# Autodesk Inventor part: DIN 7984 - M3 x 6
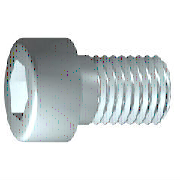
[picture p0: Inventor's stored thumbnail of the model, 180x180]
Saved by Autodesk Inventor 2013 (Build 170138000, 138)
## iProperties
IsCustomPart: 0
Created: 2012-02
Part Number: DIN 7984 - M3 x 6
Material: Steel, Mild
Description: Cylinder Head Cap Screw
Document SubType Name: Modeling
Standard: DIN 7984
Designer: rYan
Standard Revision: 1985
Standards Organization: DIN
Language: en-US
Size Designation: M3 x 6
Categories: <MemberInstance><Categories><Category DisplayName="Fasteners" InternalName="e4da775c-781d-43d5-af7c-5136215cf5a6" Mnemonic="FSTN"><Category DisplayName="Bolts"
Density: 7.86 g/cm^3
Mass: 0.653232 g
Surface Area: 1.45477 cm^2
Volume: 0.0831084 cm^3
Author: rYan
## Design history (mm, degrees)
sketch "Sketch1"
  geometry: L1 (0.167, 0)-(6, 0); L2 (6, 0)-(6, 1.5); L3 (6, 1.5)-(1.5, 1.5); L4 (1.5, 1.5)-(1.193, 1.5); L5 (1.193, 1.5)-(0, 1.5); L6 (0, 1.5)-(0, 2.75); L7 (0, 2.75)-(-2, 2.75); L8 (-2, 2.75)-(-2, 1.155); L9 (-2, 1.155)-(-0.5, 1.155); L10 (-0.5, 1.155)-(0.167, 0); L11 (-3.6, 0)-(7.6, 0) reference; L12 (0, -0.55)-(0, 3.3) reference; L13 (1.5, 1.5)-(0, 1.5)
  constraints: 22 end point, 6 parallel, 2 collinear, 2 perpendicular, 1 horizontal, 1 point on line
  dimensions: "d1" = 4.5 distance from line of L3.end L2 (= GEL); "d2" = 0.30683 distance of L4.end L3.end (computed from GAL); "d3" = 2 distance between parallel lines of L8 L6 (= KOH); "d4" = 1.5 distance of L8.end L9.end (= INTI); "d5" = 60 deg angle of L10 L1; "d6" = 3 diameter of L3 L1 (= GD); "d7" = 3 diameter of L5 L1 (= BDM); "d8" = 2.3094 diameter of L9 L1 (= 1.1547 x SW); "d9" = 5.5 diameter of L7 L1 (= KOD); "d26" = 6 distance between parallel lines of L12 L2 (= NLG)
revolve "Body" sketch "Sketch1" stored, may be unused: angle "d10" = 90 deg
sketch "Sketch2"
  geometry: L1 (0, -3.85)-(0, 3.85) reference; L2 (-3.85, 0)-(3.85, 0) reference; L3 (1.155, 0)-(0.577, -1); L4 (0.577, -1)-(-0.577, -1); L5 (-0.577, -1)-(-1.155, 0); L6 (-1.155, 0)-(-0.577, 1); L7 (-0.577, 1)-(0.577, 1); L8 (0.577, 1)-(1.155, 0); 2 further points
  constraints: 12 end point, 1 coincident, 1 horizontal alignment, 1 point on line, 12 other
extrude "Slot" join sketch "Sketch2" stored distance "d11" = 10; taper "d12" = 0 deg
workplane "Work Plane1"
fillet "Fillet2" dims "d30" = 0.1 (= R)
body "Solid1"
fillet "Fillet1" dims "d17" = 0.3 (= RR)
feature "Thread" dims "d13" = 4.5 (= GEL), "d14" = 0
chamfer "Chamfer1" distance "d15" = 0.30673 (= -0.5 x SPD + 0.5 x GD); stored, may be unused: second distance "d16" = 0.30673 (= GUL), angle "d27" = 45 deg
other parameters: "GD" = 3 (= NND) [user parameter; used in 2 equation terms], "NLG" = 6 [user parameter; used in 1 equation term], "GEL" = 4.5 [user parameter; used in 2 equation terms], "KOD" = 5.5 [user parameter; used in 1 equation term], "KOH" = 2 [user parameter; used in 1 equation term], "INTI" = 1.5 [user parameter; used in 1 equation term], "GAL" = 0.30673 (= 0.61345 x PTC) [user parameter; used in 1 equation term], "GUL" = 0.30673 (= 0.61345 x PTC) [user parameter; used in 1 equation term], "BDM" = 3 (= NND) [user parameter; used in 1 equation term], "SW" = 2 [user parameter; used in 2 equation terms], "RR" = 0.3 [user parameter; used in 1 equation term], "SPD" = 2.38655 (= NND - 1.2269 x PTC) [user parameter; used in 1 equation term], "d19" = 0, "d28" = 0, "d29" = 0, "R" = 0.1 [user parameter; used in 1 equation term], "TOA" = 30 deg [user parameter], "GD1" = 2.38655 (= THREADDIA - 1.2269 x PTC) [user parameter], "THREADDIA" = 3 [user parameter; used in 1 equation term], "FAWI" = 45 deg [user parameter], "ANG" = 120 deg [user parameter], "PTC" = 0.5 [user parameter; used in 5 equation terms], "NND" = 3 [user parameter; used in 3 equation terms], "E0" = 2.31 (= 1.155 x SW) [user parameter]
